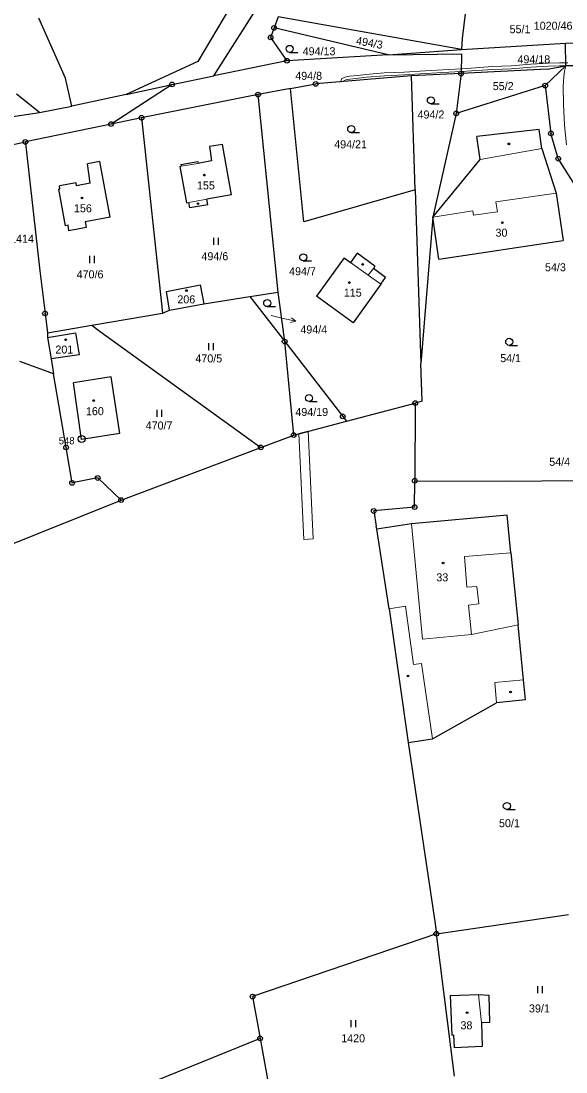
# Model space of a CAD drawing. Extents: x -601131 to -597152, y -1058536 to -1055911.
# Drawn here: x -599584.4 to -599468.7, y -1057278.4 to -1057055.1 of the extents above; entities that cross this region are included whole.
import ezdxf
from ezdxf.enums import TextEntityAlignment as Align

# ---------------------------------------------------------------- set-up
doc = ezdxf.new("R2010")
doc.units = 0
doc.header["$LTSCALE"] = 0.68
for name, color, linetype, lineweight in [('1', 7, 'Continuous', 25), ('13', 7, 'Continuous', 13), ('3', 7, 'Continuous', 25), ('4', 7, 'Continuous', 13), ('5', 7, 'Continuous', 25), ('7', 7, 'Continuous', 13), ('8', 7, 'Continuous', 25)]:
    doc.layers.add(name, color=color, linetype=linetype, lineweight=lineweight)
doc.layers.add('2', color=7, linetype='Continuous')

msp = doc.modelspace()

# ---------------------------------------------------------------- linework, layer by layer
at = {"layer": '1'}
for p, q in [((-599527.65, -1057031.27), (-599546.87, -1057063.62)), ((-599543.49, -1057066.69), (-599523.14, -1057034.64)), ((-599489.38, -1057047.68), (-599490.76, -1057058.76)), ((-599574.95, -1057067.21), (-599580.63, -1057054.46)), ((-599529.83, -1057054.16), (-599530.69, -1057056.51)), ((-599490.87, -1057061.08), (-599529.83, -1057054.16)), ((-599530.69, -1057056.51), (-599531.42, -1057058.52)), ((-599506.5, -1057062.21), (-599530.69, -1057056.51)), ((-599531.42, -1057058.52), (-599527.97, -1057063.49)), ((-599490.76, -1057058.76), (-599490.87, -1057061.08)), ((-599490.87, -1057061.08), (-599468.81, -1057059.73)), ((-599468.81, -1057059.73), (-599464.17, -1057059.6)), ((-599468.73, -1057064.59), (-599468.81, -1057059.73)), ((-599506.5, -1057062.21), (-599527.97, -1057063.49)), ((-599506.5, -1057062.21), (-599490.87, -1057061.08)), ((-599506.5, -1057062.21), (-599490.89, -1057062.01)), ((-599490.89, -1057062.01), (-599491, -1057066.22)), ((-599546.87, -1057063.62), (-599562.07, -1057070.7)), ((-599527.97, -1057063.49), (-599543.49, -1057066.69)), ((-599473.14, -1057068.77), (-599468.73, -1057064.59)), ((-599472.72, -1057065.31), (-599468.73, -1057064.59)), ((-599464, -1057064.55), (-599468.73, -1057064.59)), ((-599552.36, -1057068.52), (-599543.49, -1057066.69)), ((-599501.52, -1057066.71), (-599521.85, -1057068.41)), ((-599491, -1057066.22), (-599501.52, -1057066.71)), ((-599500.72, -1057090.95), (-599501.52, -1057066.71)), ((-599491, -1057066.22), (-599492.03, -1057074.69)), ((-599472.72, -1057065.31), (-599491, -1057066.22)), ((-599573.6, -1057073.18), (-599574.95, -1057067.21)), ((-599552.36, -1057068.52), (-599565.3, -1057076.94)), ((-599562.07, -1057070.7), (-599552.36, -1057068.52)), ((-599527.18, -1057069.39), (-599521.85, -1057068.41)), ((-599473.14, -1057068.77), (-599492.03, -1057074.69)), ((-599473.14, -1057068.77), (-599471.91, -1057078.93)), ((-599580.47, -1057074.49), (-599585.38, -1057070.61)), ((-599562.07, -1057070.7), (-599573.6, -1057073.18)), ((-599534.09, -1057070.67), (-599558.82, -1057075.62)), ((-599527.18, -1057069.39), (-599534.09, -1057070.67)), ((-599529.85, -1057112.7), (-599534.09, -1057070.67)), ((-599524.36, -1057097.73), (-599527.18, -1057069.39)), ((-599580.47, -1057074.49), (-599573.6, -1057073.18)), ((-599590.12, -1057075.92), (-599580.47, -1057074.49)), ((-599558.82, -1057075.62), (-599565.3, -1057076.94)), ((-599558.82, -1057075.62), (-599554.4, -1057117.1)), ((-599492.03, -1057074.69), (-599497.02, -1057096.7)), ((-599565.3, -1057076.94), (-599583.48, -1057080.75)), ((-599474.43, -1057078.1), (-599487.62, -1057079.61)), ((-599486.93, -1057084.51), (-599487.62, -1057079.61)), ((-599473.86, -1057082.13), (-599474.43, -1057078.1)), ((-599470.35, -1057084.3), (-599471.91, -1057078.93)), ((-599590.99, -1057082.33), (-599583.48, -1057080.75)), ((-599583.48, -1057080.75), (-599583.38, -1057081.66)), ((-599583.38, -1057081.66), (-599580.41, -1057108.12)), ((-599541.67, -1057081.28), (-599544.43, -1057081.7)), ((-599544.43, -1057081.7), (-599543.94, -1057084.78)), ((-599539.75, -1057091.97), (-599541.67, -1057081.28)), ((-599473.86, -1057082.13), (-599470.79, -1057091.66)), ((-599497.02, -1057096.7), (-599486.93, -1057084.51)), ((-599464.62, -1057093.31), (-599470.35, -1057084.3)), ((-599567.68, -1057084.91), (-599570.32, -1057085.4)), ((-599569.7, -1057089.54), (-599570.32, -1057085.4)), ((-599565.49, -1057096.73), (-599567.68, -1057084.91)), ((-599550.73, -1057085.98), (-599550.42, -1057085.92)), ((-599550.73, -1057085.98), (-599549.3, -1057093.71)), ((-599550.49, -1057085.57), (-599546.91, -1057084.92)), ((-599550.49, -1057085.57), (-599550.42, -1057085.92)), ((-599546.91, -1057084.92), (-599546.84, -1057085.3)), ((-599543.94, -1057084.78), (-599546.84, -1057085.3)), ((-599576.47, -1057090.75), (-599576.14, -1057090.69)), ((-599576.47, -1057090.75), (-599575.03, -1057098.56)), ((-599572.7, -1057089.46), (-599576.25, -1057090.1)), ((-599576.14, -1057090.69), (-599576.25, -1057090.1)), ((-599572.6, -1057090.06), (-599572.7, -1057089.46)), ((-599569.7, -1057089.54), (-599572.6, -1057090.06)), ((-599500.72, -1057090.95), (-599524.36, -1057097.73)), ((-599500.72, -1057090.95), (-599499.51, -1057127.85)), ((-599549.3, -1057093.71), (-599548.77, -1057093.61)), ((-599548.56, -1057094.77), (-599548.77, -1057093.61)), ((-599539.75, -1057091.97), (-599544.98, -1057092.92)), ((-599544.77, -1057094.08), (-599544.98, -1057092.92)), ((-599470.79, -1057091.66), (-599469.33, -1057101.69)), ((-599544.77, -1057094.08), (-599548.56, -1057094.77)), ((-599565.49, -1057096.73), (-599570.8, -1057097.75)), ((-599570.8, -1057097.75), (-599570.57, -1057098.95)), ((-599497.02, -1057096.7), (-599499.51, -1057127.85)), ((-599495.68, -1057105.67), (-599497.02, -1057096.7)), ((-599574.43, -1057098.44), (-599575.03, -1057098.56)), ((-599574.23, -1057099.6), (-599574.43, -1057098.44)), ((-599570.57, -1057098.95), (-599574.23, -1057099.6)), ((-599495.68, -1057105.67), (-599469.33, -1057101.69)), ((-599513.08, -1057104.39), (-599514.45, -1057106.33)), ((-599509.27, -1057107.17), (-599513.08, -1057104.39)), ((-599515.81, -1057105.37), (-599521.7, -1057113.52)), ((-599515.81, -1057105.37), (-599514.45, -1057106.33)), ((-599580.41, -1057108.12), (-599579.32, -1057117.18)), ((-599509.27, -1057107.17), (-599509.6, -1057107.61)), ((-599507.05, -1057109.55), (-599509.6, -1057107.61)), ((-599553.56, -1057112.52), (-599546.36, -1057111.1)), ((-599546.36, -1057111.1), (-599545.57, -1057115.11)), ((-599508.06, -1057110.97), (-599513.9, -1057119.15)), ((-599508.06, -1057110.97), (-599507.05, -1057109.55)), ((-599552.87, -1057116.49), (-599553.56, -1057112.52)), ((-599545.57, -1057115.11), (-599535.82, -1057113.62)), ((-599535.82, -1057113.62), (-599529.85, -1057112.7)), ((-599535.82, -1057113.62), (-599528.44, -1057123.15)), ((-599528.44, -1057123.15), (-599529.85, -1057112.7)), ((-599513.9, -1057119.15), (-599521.7, -1057113.52)), ((-599552.87, -1057116.49), (-599545.57, -1057115.11)), ((-599579.32, -1057117.18), (-599578.82, -1057121.33)), ((-599569.41, -1057119.7), (-599554.4, -1057117.1)), ((-599554.4, -1057117.1), (-599552.87, -1057116.49)), ((-599578.82, -1057121.33), (-599569.41, -1057119.7)), ((-599569.41, -1057119.7), (-599567.59, -1057121.02)), ((-599578.82, -1057121.33), (-599578.81, -1057122.33)), ((-599578.81, -1057122.33), (-599578.03, -1057126.86)), ((-599567.59, -1057121.02), (-599533.52, -1057145.66)), ((-599528.44, -1057123.15), (-599516.12, -1057139.06)), ((-599526.52, -1057143.02), (-599528.44, -1057123.15)), ((-599578.03, -1057126.86), (-599577.49, -1057130.04)), ((-599577.49, -1057130.04), (-599584.66, -1057127.37)), ((-599499.25, -1057135.83), (-599499.51, -1057127.85)), ((-599574.84, -1057145.64), (-599577.49, -1057130.04)), ((-599565.31, -1057130.67), (-599573.27, -1057131.93)), ((-599563.41, -1057142.69), (-599565.31, -1057130.67)), ((-599571.6, -1057143.94), (-599573.27, -1057131.93)), ((-599499.25, -1057135.83), (-599500.72, -1057136.23)), ((-599515.33, -1057140.08), (-599500.72, -1057136.23)), ((-599500.72, -1057136.23), (-599500.82, -1057152.74)), ((-599526.52, -1057143.02), (-599515.33, -1057140.08)), ((-599516.12, -1057139.06), (-599515.33, -1057140.08)), ((-599563.41, -1057142.69), (-599571.6, -1057143.94)), ((-599533.52, -1057145.66), (-599526.52, -1057143.02)), ((-599573.56, -1057153.2), (-599574.84, -1057145.64)), ((-599563.16, -1057156.84), (-599533.52, -1057145.66)), ((-599568.13, -1057152.15), (-599573.56, -1057153.2)), ((-599563.16, -1057156.84), (-599568.13, -1057152.15)), ((-599500.85, -1057158.33), (-599500.82, -1057152.74)), ((-599500.82, -1057152.74), (-599481.42, -1057152.83)), ((-599481.42, -1057152.83), (-599466.3, -1057152.69)), ((-599629.13, -1057183.37), (-599563.16, -1057156.84)), ((-599500.85, -1057158.33), (-599509.52, -1057159.16)), ((-599509.52, -1057159.16), (-599509.01, -1057162.37)), ((-599481.21, -1057160.04), (-599501.49, -1057161.92)), ((-599480.43, -1057168.08), (-599481.21, -1057160.04)), ((-599508.91, -1057163.04), (-599509.01, -1057162.37)), ((-599501.49, -1057161.92), (-599508.91, -1057163.04)), ((-599506.27, -1057179.94), (-599508.91, -1057163.04)), ((-599480.43, -1057168.08), (-599478.88, -1057183.35)), ((-599506.27, -1057179.94), (-599502.2, -1057208.33)), ((-599477.76, -1057195.01), (-599478.88, -1057183.35)), ((-599477.34, -1057199.28), (-599477.76, -1057195.01)), ((-599497.04, -1057207.59), (-599483.5, -1057199.89)), ((-599477.34, -1057199.28), (-599483.5, -1057199.89)), ((-599502.2, -1057208.33), (-599497.04, -1057207.59)), ((-599502.2, -1057208.33), (-599496.51, -1057246.86)), ((-599496.24, -1057248.99), (-599468.22, -1057244.89)), ((-599496.51, -1057246.86), (-599496.24, -1057248.99)), ((-599496.24, -1057248.99), (-599535.27, -1057262.34)), ((-599492.41, -1057279.26), (-599496.24, -1057248.99)), ((-599535.27, -1057262.34), (-599533.67, -1057271.24)), ((-599493.33, -1057262.13), (-599487.28, -1057261.93)), ((-599493.33, -1057262.13), (-599492.96, -1057270.51)), ((-599487.28, -1057261.93), (-599485.11, -1057262.07)), ((-599485.11, -1057262.07), (-599484.94, -1057267.86)), ((-599484.94, -1057267.86), (-599486.63, -1057267.95)), ((-599486.63, -1057267.95), (-599486.49, -1057272.96)), ((-599533.67, -1057271.24), (-599655.03, -1057320.42)), ((-599533.67, -1057271.24), (-599530.2, -1057290.54)), ((-599492.96, -1057270.51), (-599492.6, -1057270.49)), ((-599492.6, -1057270.49), (-599492.45, -1057273.26)), ((-599486.49, -1057272.96), (-599492.45, -1057273.26))]:
    msp.add_line(p, q, dxfattribs=at)
msp.add_lwpolyline([(-599578.81, -1057122.33), (-599572.84, -1057121.28), (-599572.1, -1057125.95), (-599578.03, -1057126.86)], dxfattribs=at)
at = {"layer": '13'}
for points in [[(-599468.34, -1057063.93), (-599468.74, -1057063.94), (-599470.11, -1057063.97), (-599472.45, -1057064.02), (-599476.15, -1057064.25), (-599480.33, -1057064.58), (-599484.32, -1057064.72), (-599488.84, -1057065.06), (-599490.97, -1057065.18), (-599493.62, -1057065.33), (-599498.61, -1057065.62), (-599503.04, -1057065.91), (-599507.31, -1057066.07), (-599511.18, -1057066.39), (-599512.88, -1057066.63), (-599514.66, -1057066.8), (-599515.64, -1057066.99), (-599516.35, -1057067.36), (-599516.52, -1057067.96), (-599516.41, -1057067.95), (-599516.07, -1057067.93), (-599515.88, -1057067.91), (-599515.85, -1057067.78), (-599515.44, -1057067.57), (-599514.58, -1057067.4), (-599512.8, -1057067.23), (-599511.12, -1057066.99), (-599507.27, -1057066.67), (-599503, -1057066.51), (-599498.57, -1057066.22), (-599493.58, -1057065.93), (-599490.99, -1057065.78), (-599488.8, -1057065.66), (-599484.28, -1057065.32), (-599480.29, -1057065.18), (-599476.11, -1057064.85), (-599472.43, -1057064.62), (-599470.09, -1057064.57), (-599468.73, -1057064.59), (-599468.07, -1057064.58)], [(-599468.07, -1057064.58), (-599468.73, -1057064.59), (-599469.03, -1057065.7), (-599469.17, -1057066.9), (-599469.32, -1057068.92), (-599469.24, -1057072.76), (-599469.02, -1057077.16), (-599468.62, -1057081.36)]]:
    msp.add_lwpolyline(points, dxfattribs=at)
msp.add_lwpolyline([(-599522.37, -1057165.11), (-599523.46, -1057142.21), (-599525.43, -1057142.73), (-599524.37, -1057165.2)], close=True, dxfattribs=at)
at = {"layer": '3'}
for p, q in [((-599527.383, -1057061.73), (-599525.633, -1057061.73)), ((-599497.403, -1057072.67), (-599495.653, -1057072.67)), ((-599514.313, -1057078.77), (-599512.563, -1057078.77)), ((-599543.491, -1057102.61), (-599543.491, -1057101.11)), ((-599542.49, -1057102.61), (-599542.49, -1057101.11)), ((-599569.821, -1057106.47), (-599569.821, -1057104.97)), ((-599568.82, -1057106.47), (-599568.82, -1057104.97)), ((-599524.503, -1057106.01), (-599522.753, -1057106.01)), ((-599532.143, -1057115.74), (-599530.393, -1057115.74)), ((-599544.541, -1057124.98), (-599544.541, -1057123.48)), ((-599543.54, -1057124.98), (-599543.54, -1057123.48)), ((-599480.773, -1057123.97), (-599479.023, -1057123.97)), ((-599523.263, -1057135.92), (-599521.513, -1057135.92)), ((-599555.531, -1057139.19), (-599555.531, -1057137.69)), ((-599554.53, -1057139.19), (-599554.53, -1057137.69)), ((-599481.273, -1057222.59), (-599479.523, -1057222.59)), ((-599474.721, -1057261.64), (-599474.721, -1057260.14)), ((-599473.72, -1057261.64), (-599473.72, -1057260.14)), ((-599514.301, -1057268.83), (-599514.301, -1057267.33)), ((-599513.3, -1057268.83), (-599513.3, -1057267.33))]:
    msp.add_line(p, q, dxfattribs=at)
for centre in [(-599527.3829, -1057060.9798), (-599497.4029, -1057071.9198), (-599514.3129, -1057078.0198), (-599524.5029, -1057105.2598), (-599532.1429, -1057114.9898), (-599480.7729, -1057123.2198), (-599523.2629, -1057135.1698), (-599481.2729, -1057221.8398)]:
    msp.add_circle(centre, 0.75, dxfattribs=at)
at = {"layer": '4'}
for p, q in [((-599486.93, -1057084.51), (-599473.86, -1057082.13)), ((-599546.84, -1057085.3), (-599550.42, -1057085.92)), ((-599544.98, -1057092.92), (-599548.77, -1057093.61)), ((-599470.79, -1057091.66), (-599483.58, -1057093.5)), ((-599483.28, -1057095.57), (-599483.58, -1057093.5)), ((-599497.02, -1057096.7), (-599488.5, -1057095.35)), ((-599488.5, -1057095.35), (-599488.34, -1057096.33)), ((-599488.34, -1057096.33), (-599483.28, -1057095.57)), ((-599510.69, -1057109.06), (-599514.45, -1057106.33)), ((-599509.6, -1057107.61), (-599510.69, -1057109.06)), ((-599508.06, -1057110.97), (-599510.69, -1057109.06)), ((-599501.49, -1057161.92), (-599499.16, -1057186.41)), ((-599480.43, -1057168.08), (-599490.3, -1057168.84)), ((-599490.3, -1057168.84), (-599489.79, -1057175.37)), ((-599489.79, -1057175.37), (-599487.65, -1057175.2)), ((-599487.65, -1057175.2), (-599487.24, -1057178.92)), ((-599502.76, -1057179.39), (-599506.27, -1057179.94)), ((-599502.76, -1057179.39), (-599501.11, -1057191.77)), ((-599487.24, -1057178.92), (-599489.39, -1057179.14)), ((-599489.39, -1057179.14), (-599488.77, -1057185.39)), ((-599478.88, -1057183.35), (-599488.77, -1057185.39)), ((-599488.77, -1057185.39), (-599499.16, -1057186.41)), ((-599499.37, -1057191.54), (-599501.11, -1057191.77)), ((-599497.04, -1057207.59), (-599499.37, -1057191.54)), ((-599477.76, -1057195.01), (-599483.85, -1057195.59)), ((-599483.85, -1057195.59), (-599483.5, -1057199.89)), ((-599486.63, -1057267.95), (-599487.28, -1057261.93))]:
    msp.add_line(p, q, dxfattribs=at)
at = {"layer": '5'}
for centre in [(-599480.8368, -1057081.1592), (-599545.4868, -1057087.7992), (-599571.4768, -1057092.6492), (-599546.8268, -1057093.8692), (-599482.2468, -1057097.8992), (-599511.8968, -1057106.7792), (-599514.7068, -1057110.6292), (-599549.2968, -1057112.3192), (-599574.9468, -1057122.7892), (-599568.9768, -1057135.6892), (-599494.8068, -1057170.2192), (-599502.2568, -1057194.2092), (-599480.4868, -1057197.6092), (-599489.7068, -1057265.7392)]:
    msp.add_circle(centre, 0.175, dxfattribs=at)
at = {"layer": '7'}
msp.add_line((-599526.106, -1057118.855), (-599526.969, -1057118.142), dxfattribs=at)
msp.add_lwpolyline([(-599531.29, -1057117.64), (-599529.03, -1057118.18), (-599526.106, -1057118.855), (-599527.194, -1057119.118)], dxfattribs=at)
at = {"layer": '8'}
for centre, radius in [((-599530.69, -1057056.5099), 0.5), ((-599530.69, -1057056.5099), 0.0303), ((-599531.42, -1057058.5199), 0.5), ((-599531.42, -1057058.5199), 0.0303), ((-599527.97, -1057063.4899), 0.5), ((-599527.97, -1057063.4899), 0.0303), ((-599491, -1057066.2199), 0.5), ((-599491, -1057066.2199), 0.0303), ((-599552.36, -1057068.5199), 0.5), ((-599552.36, -1057068.5199), 0.0303), ((-599521.85, -1057068.4099), 0.5), ((-599521.85, -1057068.4099), 0.0303), ((-599473.14, -1057068.7699), 0.5), ((-599473.14, -1057068.7699), 0.0303), ((-599534.09, -1057070.6699), 0.5), ((-599534.09, -1057070.6699), 0.0303), ((-599558.82, -1057075.6199), 0.5), ((-599558.82, -1057075.6199), 0.0303), ((-599492.03, -1057074.6899), 0.5), ((-599492.03, -1057074.6899), 0.0303), ((-599565.3, -1057076.9399), 0.5), ((-599565.3, -1057076.9399), 0.0303), ((-599471.91, -1057078.9299), 0.5), ((-599471.91, -1057078.9299), 0.0303), ((-599583.48, -1057080.7499), 0.5), ((-599583.48, -1057080.7499), 0.0303), ((-599470.35, -1057084.2999), 0.5), ((-599470.35, -1057084.2999), 0.0303), ((-599579.32, -1057117.1799), 0.5), ((-599579.32, -1057117.1799), 0.0303), ((-599528.44, -1057123.1499), 0.5), ((-599528.44, -1057123.1499), 0.0303), ((-599500.72, -1057136.2299), 0.5), ((-599500.72, -1057136.2299), 0.0303), ((-599516.12, -1057139.0599), 0.5), ((-599516.12, -1057139.0599), 0.0303), ((-599526.52, -1057143.0199), 0.5), ((-599571.55, -1057143.8598), 0.75), ((-599571.55, -1057143.8598), 0.03), ((-599526.52, -1057143.0199), 0.0303), ((-599574.84, -1057145.6399), 0.5), ((-599574.84, -1057145.6399), 0.0303), ((-599533.52, -1057145.6599), 0.5), ((-599533.52, -1057145.6599), 0.0303), ((-599568.13, -1057152.1499), 0.5), ((-599573.56, -1057153.1999), 0.5), ((-599573.56, -1057153.1999), 0.0303), ((-599568.13, -1057152.1499), 0.0303), ((-599500.82, -1057152.7399), 0.5), ((-599500.82, -1057152.7399), 0.0303), ((-599563.16, -1057156.8399), 0.5), ((-599563.16, -1057156.8399), 0.0303), ((-599500.85, -1057158.3299), 0.5), ((-599500.85, -1057158.3299), 0.0303), ((-599509.52, -1057159.1599), 0.5), ((-599509.52, -1057159.1599), 0.0303), ((-599496.24, -1057248.9899), 0.5), ((-599496.24, -1057248.9899), 0.0303), ((-599535.27, -1057262.3399), 0.5), ((-599535.27, -1057262.3399), 0.0303), ((-599533.67, -1057271.2399), 0.5), ((-599533.67, -1057271.2399), 0.0303)]:
    msp.add_circle(centre, radius, dxfattribs=at)

# ---------------------------------------------------------------- texts
at = {"layer": '2'}
for s, p in [('1020/46', (-599467.34, -1057056.905)), ('54/3', (-599468.749, -1057108.225)), ('54/4', (-599467.839, -1057149.564))]:
    msp.add_text(s, height=1.7, dxfattribs=at).set_placement(p, align=Align.RIGHT)
for s, p in [('55/1', (-599480.69, -1057057.645)), ('494/13', (-599524.62, -1057062.324)), ('494/18', (-599479.02, -1057064.045)), ('494/8', (-599526.19, -1057067.545)), ('55/2', (-599484.26, -1057069.735)), ('494/2', (-599500.23, -1057075.765)), ('494/21', (-599517.92, -1057082.094)), ('155', (-599547.06, -1057090.834)), ('156', (-599573.17, -1057095.695)), ('30', (-599483.68, -1057100.875)), ('494/6', (-599546.11, -1057105.875)), ('470/6', (-599572.6, -1057109.725)), ('494/7', (-599527.5, -1057109.074)), ('115', (-599515.88, -1057113.615)), ('494/4', (-599525.11, -1057121.445)), ('470/5', (-599547.39, -1057127.594)), ('54/1', (-599482.69, -1057127.535)), ('160', (-599570.63, -1057138.804)), ('494/19', (-599526.18, -1057138.975)), ('470/7', (-599557.95, -1057141.844)), ('33', (-599496.24, -1057174.104)), ('50/1', (-599482.94, -1057226.344)), ('39/1', (-599476.57, -1057265.705)), ('38', (-599491.12, -1057269.285))]:
    msp.add_text(s, height=1.7, dxfattribs=at).set_placement(p)
msp.add_text('494/3', height=1.7, rotation=350, dxfattribs=at).set_placement((-599513.393, -1057060.008))
for s, p in [('1414', (-599584.2, -1057102.172)), ('206', (-599549.329, -1057115.045)), ('201', (-599575.219, -1057125.705)), ('1420', (-599513.91, -1057272.062))]:
    msp.add_text(s, height=1.7, dxfattribs=at).set_placement(p, align=Align.CENTER)
at = {"layer": '8'}
msp.add_text('548', height=1.5, dxfattribs=at).set_placement((-599573.049, -1057144.977), align=Align.RIGHT)

doc.saveas('drawing.dxf')
